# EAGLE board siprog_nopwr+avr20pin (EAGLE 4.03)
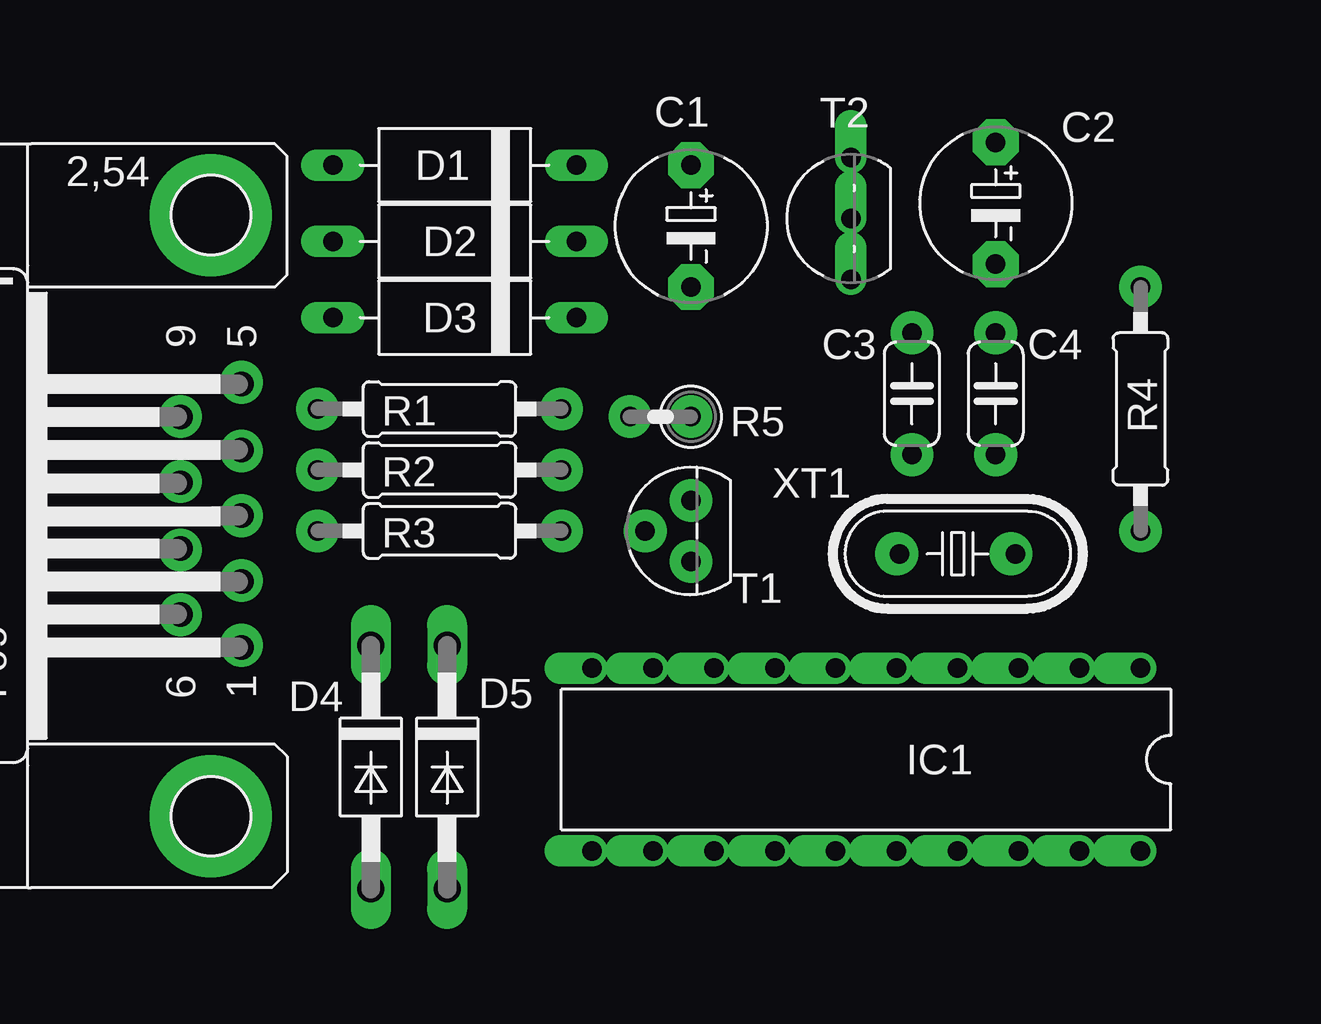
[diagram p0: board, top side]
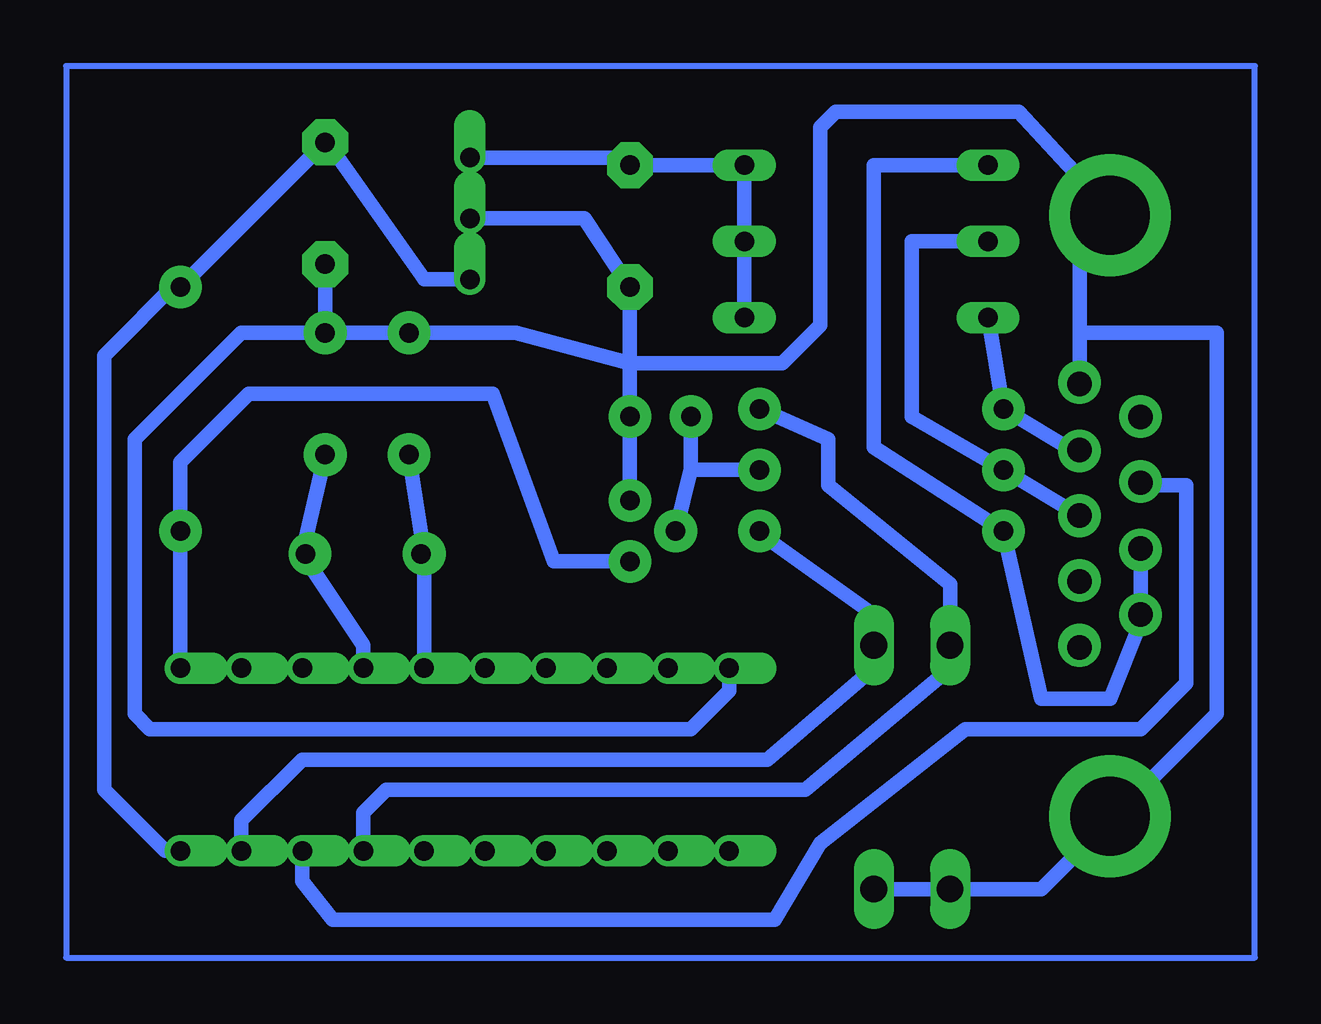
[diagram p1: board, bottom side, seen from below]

No outline drawn. Coordinates in mm, seen from the top.
Copper layers used: Bottom

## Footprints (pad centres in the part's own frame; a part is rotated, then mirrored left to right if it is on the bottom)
E5-6 = drill 0.813 pad 1.905 octagon: + -2.54,0; - 2.54,0
C050-024X044 = drill 0.813 octagon: 1 -2.54,0; 2 2.54,0
F09HP = drill 1.016 octagon: 1 -5.486,-1.27; 2 -2.743,-1.27; 3 0,-1.27; 4 2.743,-1.27; 5 5.486,-1.27; 6 -4.115,1.27; 7 -1.372,1.27; 8 1.372,1.27; 9 4.115,1.27 | drill 3.302 pad 5.08 round: G1 -12.522,0; G2 12.522,0
D-10 = drill 0.813 long: A 5.08,0; C -5.08,0
DO41-10 = drill 1.118 long: A 5.08,0; C -5.08,0
DIL-20 = drill 0.813 offset: 1 -11.43,-3.81; 2 -8.89,-3.81; 3 -6.35,-3.81; 4 -3.81,-3.81; 5 -1.27,-3.81; 6 1.27,-3.81; 7 3.81,-3.81; 8 6.35,-3.81; 9 8.89,-3.81; 10 11.43,-3.81; 11 11.43,3.81; 12 8.89,3.81; 13 6.35,3.81; 14 3.81,3.81; 15 1.27,3.81; 16 -1.27,3.81; 17 -3.81,3.81; 18 -6.35,3.81; 19 -8.89,3.81; 20 -11.43,3.81
0207/10 = drill 0.813 octagon: 1 -5.08,0; 2 5.08,0
0207/2V = drill 0.813 octagon: 1 -1.27,0; 2 1.27,0
TO92 = drill 0.813 octagon: 1 1.27,0; 2 0,1.905; 3 -1.27,0
TO92- = drill 0.813 offset: 1 2.54,-1.27; 2 0,-1.27; 3 -2.54,-1.27
HC49U-V = drill 0.813 round: 1 -2.413,0; 2 2.413,0

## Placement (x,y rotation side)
C1  [E5-6]  36.51,57.78 270 top
C2  [E5-6]  49.21,58.74 270 top
C3  [C050-024X044]  45.72,50.8 90 top
C4  [C050-024X044]  49.21,50.8 90 top
COM1  [F09HP]  16.51,45.72 90 top
D1  [D-10]  26.67,60.33 180 top
D2  [D-10]  26.67,57.15 180 top
D3  [D-10]  26.67,53.98 180 top
D4  [DO41-10]  23.18,35.24 270 top
D5  [DO41-10]  26.35,35.24 270 top
IC1  [DIL-20]  43.81,35.56 180 top
R1  [0207/10]  26.04,50.16 0 top
R2  [0207/10]  26.04,47.62 0 top
R3  [0207/10]  26.04,45.09 0 top
R4  [0207/10]  55.24,50.16 90 top
R5  [0207/2V]  35.24,49.85 180 top
T1  [TO92]  36.51,45.09 90 top
T2  [TO92-]  41.91,58.1 90 top
XT1  [HC49U-V]  47.62,44.13 0 top

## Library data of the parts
C1-C4 R1-R5 = rcl
COM1 = con-subd
D1-D5 = diode
IC1 = ic-package
T1 = transistor-npn
T2 = transistor-pnp
XT1 = crystal

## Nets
S$1: IC1.18
S$2: C2.-
S$3: D1.A
S$4: D3.A
S$5: COM1.3 D2.A
S$6: D5.C IC1.19 R3.2
S$7: D5.A
S$8: R2.2 T1.2
S$9: IC1.4
S$10: C1.- D4.A T1.1 T2.2
S$11: D4.C IC1.17 R1.2
S$12: IC1.20 T2.3
S$13: C1.+ D1.C D2.C D3.C
S$14: IC1.1 T1.3
S$15: IC1.5
S$16: C4.1
S$31: T2.1

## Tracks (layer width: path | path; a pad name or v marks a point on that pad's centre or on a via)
S$1
  Bottom 0.61: IC1.18 50.16,30.48 48.9,28.89 30.48,28.89 28.57,32.07 22.54,36.83 15.24,36.83 13.34,38.73 13.34,46.99 15.24,46.99
S$2
  Bottom 0.61: 32.38,39.37 32.38,38.42 33.97,36.83 56.52,36.83 57.15,37.47 57.15,48.9 52.7,53.34 49.21,53.34 | 49.21,53.34 41.27,53.34 | C2.- 49.21,53.34
S$3
  Bottom 0.61: D1.A 26.35,60.33 26.35,48.58 20.95,45.09 19.37,38.1 16.51,38.1 15.24,41.27
S$4
  Bottom 0.61: 17.78,48.26 20.95,50.16 D3.A
S$5
  Bottom 0.61: COM1.3 20.95,47.62 24.77,49.85 24.77,57.15 D2.A
S$6
  Bottom 0.406: 30.8,44.77 R3.2
  Bottom 0.61: 30.8,44.77 26.35,41.59 D5.C 26.35,39.37 30.8,35.56 50.16,35.56 52.7,33.02 IC1.19
S$8
  Bottom 0.61: T1.2 33.97,47.62 | R2.2 33.97,47.62 | 33.97,47.62 33.97,49.85
S$9
  Bottom 0.61: IC1.4 47.62,40.32 50.16,44.13
S$10
  Bottom 0.61: T2.2 38.42,58.1 C1.- 36.51,52.07 | 36.51,52.07 T1.1 | 36.51,52.07 41.27,53.34 | 36.51,52.07 30.16,52.07 28.57,53.66 28.57,61.91 27.94,62.55 20.32,62.55 16.51,58.42 | 16.51,60.33 15.24,59.69 | 14.61,58.42 15.24,59.69 | 15.24,57.15 14.61,58.42 | 16.51,60.33 17.78,60.01 18.41,58.42 | 16.51,56.52 15.24,57.15 | 16.51,58.42 16.51,56.52 | 16.51,58.42 14.61,58.42 | 16.51,58.42 16.51,60.33 | 16.51,58.42 15.24,57.15 | 16.51,58.42 15.24,59.69 | 16.51,58.42 18.41,58.42 | 17.78,57.15 16.51,58.42 | 17.78,57.15 16.51,56.52 | 17.78,57.15 18.41,58.42 | 17.78,53.34 17.78,51.44 | 17.78,53.34 17.78,57.15 | 17.78,53.34 12.06,53.34 12.06,37.47 15.24,34.29 | 16.51,34.92 17.78,34.29 | 15.24,34.29 16.51,34.92 | 14.61,33.02 15.24,34.29 | 18.41,33.02 17.78,34.29 | 17.78,31.75 18.41,33.02 | 15.24,31.75 14.61,33.02 | 16.51,33.02 15.24,34.29 | 16.51,33.02 17.78,31.75 | 16.51,33.02 16.51,34.92 | 16.51,33.02 17.78,34.29 | 16.51,33.02 18.41,33.02 | 16.51,33.02 14.61,33.02 | 16.51,33.02 15.24,31.75 | 16.51,31.43 16.51,33.02 | 16.51,31.43 15.24,31.75 | 17.78,31.75 19.37,30.16 D4.A | 17.78,31.75 16.51,31.43
S$11
  Bottom 0.61: R1.2 28.26,48.9 28.26,46.99 23.18,42.86 D4.C 23.18,39.37 29.21,34.29 46.67,34.29 47.62,33.34 IC1.17
S$12
  Bottom 0.406: IC1.20 55.88,31.75
  Bottom 0.61: T2.3 45.09,55.56 48.9,60.96 49.21,61.28 55.24,55.24 55.24,55.56 58.42,52.39 58.42,34.29 55.88,31.75
S$13
  Bottom 0.61: 43.5,60.64 37.15,60.64 C1.+ D1.C D2.C D3.C
S$14
  Bottom 0.61: T1.3 39.69,43.81 42.23,50.8 52.39,50.8 55.24,47.94 IC1.1
S$15  (via drill 0.25 pad 1.78)
  Bottom 0.61: IC1.5 v45.09,44.13 45.72,48.26
S$16
  Bottom 0.61: 50.16,44.13 C4.1
S$17  (via drill 0.25 pad 1.78)
  other vias: 49.85,44.13
S$18
  Bottom 0.61: 23.18,30.16 26.35,30.16
S$19  (via drill 0.25 pad 1.78)
  other vias: 34.61,45.09
S$20  (via drill 0.25 pad 1.78)
  other vias: 36.51,46.35
S$21  (via drill 0.25 pad 1.78)
  other vias: 49.21,53.34
S$22  (via drill 0.25 pad 1.78)
  other vias: 45.72,53.34
S$23  (via drill 0.25 pad 1.78)
  other vias: 45.72,48.26
S$24  (via drill 0.25 pad 1.78)
  other vias: 49.21,48.26
S$25  (via drill 0.25 pad 1.78)
  other vias: 55.24,45.09
S$26  (via drill 0.25 pad 1.78)
  other vias: 55.24,55.24
S$27
  Bottom 0.254: 10.48,64.45 60.01,64.45 60.01,27.3 10.48,27.3 10.48,64.45
S$28  (via drill 0.25 pad 1.78)
  other vias: 31.11,45.09
S$29  (via drill 0.25 pad 1.78)
  other vias: 31.11,47.62
S$30  (via drill 0.25 pad 1.78)
  other vias: 31.11,50.16
S$32  (via drill 0.25 pad 1.78)
  other vias: 20.95,45.09
S$33  (via drill 0.61 pad 1.78)
  Bottom 0.61: v15.24,41.59 v15.24,44.29 15.24,44.45
S$34  (via drill 0.25 pad 1.78)
  other vias: 20.95,47.62
S$35  (via drill 0.25 pad 1.78)
  other vias: 20.95,50.16
S$36  (via drill 0.25 pad 1.78)
  other vias: 36.51,43.81
S$37  (via drill 0.25 pad 1.78)
  other vias: 33.97,49.85
S$38  (via drill 0.25 pad 1.78)
  other vias: 36.51,49.85
S$39  (via drill 0.61 pad 1.78)
  other vias: 15.24,47.15
S$40  (via drill 0.61 pad 1.78)
  other vias: 15.24,49.85
S$41  (via drill 0.61 pad 1.78)
  other vias: 17.78,51.28
S$42  (via drill 0.61 pad 1.78)
  other vias: 17.78,48.42
S$43  (via drill 0.61 pad 1.78)
  other vias: 17.78,45.72
S$44  (via drill 0.61 pad 1.78)
  other vias: 17.78,43.02
S$45  (via drill 0.61 pad 1.78)
  other vias: 17.78,40.32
